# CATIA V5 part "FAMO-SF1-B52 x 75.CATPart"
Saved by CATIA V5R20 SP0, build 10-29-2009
Part number: FAMO-SF1-B52 x 75
Definition: NONE
Nomenclature: FAMO-SF1-B52 x 75
Source: Unknown
Description: FAMO-SF1-B52 x 75
Bounding box of the stored display mesh (mm): x -13 to 62, y -39.5 to 39.5, z -39.5 to 39.5
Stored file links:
  C:\Users\Utente\Desktop\IO LAVORO\3D X SITO CF\X SITO\FAMO\FAMO-SF1-B52 x 75.CATPart

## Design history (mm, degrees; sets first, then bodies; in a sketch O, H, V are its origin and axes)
Body1 "FAMO-SF1-B52 x 75" (main body)
  Solid1: solid without history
